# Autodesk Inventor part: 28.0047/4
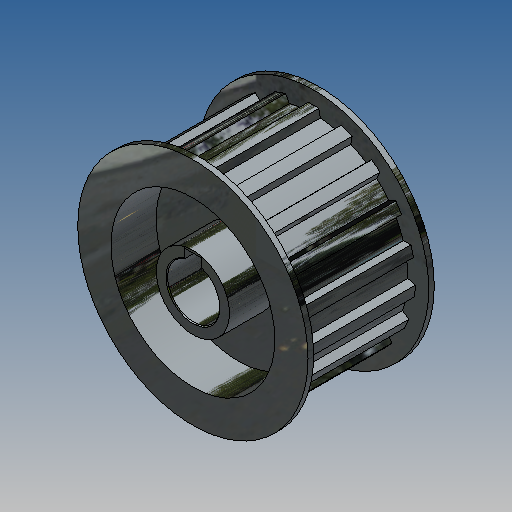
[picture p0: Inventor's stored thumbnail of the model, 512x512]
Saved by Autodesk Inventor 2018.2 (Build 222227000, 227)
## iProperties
Created: 2006-12
Document SubType Name: Modeling
Designer: Andy Moles
Material: Aluminum-6061
Part Number: 28.0047/4
Density: 2.7 g/cm^3
Description: Timing Belt Pulley T45, 15mm Bore & Key
Mass: 131.491 g
Surface Area: 244.333 cm^2
Volume: 48.7006 cm^3
Appearance: Zinc
Author: Andy Moles
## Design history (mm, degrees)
sketch "Sketch1"
  geometry: L1 (-1.927, 26.982)-(-1.524, 29.17); L2 (1.927, 26.982)-(1.524, 29.17); L3 (11.073, 27.03)-(10.707, 24.842); L4 (15.084, 22.455)-(16.683, 23.977); L5 (19.077, 22.12)-(18.136, 20.071); L6 (21.534, 16.371)-(23.587, 17.23); L7 (25.254, 14.678)-(23.643, 13.144); L8 (25.717, 8.391)-(27.944, 8.508); L9 (28.652, 5.683)-(26.63, 4.755); L10 (27.049, -0.307)-(29.196, -0.889); L11 (28.945, -3.928)-(26.741, -4.085); L12 (25.484, -9.074)-(27.339, -10.286); L13 (26.084, -13.147)-(23.954, -12.569); L14 (21.157, -16.857)-(22.493, -18.635); L15 (20.429, -20.878)-(18.546, -19.693); L16 (14.537, -22.813)-(15.224, -24.929); L17 (12.543, -26.38)-(11.147, -24.648); L18 (6.342, -26.297)-(6.304, -28.522); L19 (3.298, -29.023)-(2.54, -26.931); L20 (-2.54, -26.931)-(-3.298, -29.023); L21 (-6.304, -28.522)-(-6.342, -26.297); L22 (-11.183, -24.631)-(-12.509, -26.396); L23 (-15.224, -24.929)-(-14.537, -22.813); L24 (-18.546, -19.693)-(-20.429, -20.878); L25 (-22.494, -18.635)-(-21.157, -16.856); L26 (-23.935, -12.604)-(-26.101, -13.113); L27 (-27.325, -10.322)-(-25.484, -9.074); L28 (-26.731, -4.15)-(-28.945, -3.928); L29 (-29.196, -0.89)-(-27.049, -0.307); L30 (-26.63, 4.756)-(-28.652, 5.685); L31 (-27.892, 8.674)-(-25.696, 8.455); L32 (-23.643, 13.144)-(-25.254, 14.679); L33 (-23.587, 17.23)-(-21.534, 16.371); L34 (-18.094, 20.109)-(-19.119, 22.083); L35 (-16.714, 23.955)-(-15.052, 22.477); L36 (-10.707, 24.842)-(-11.073, 27.03); L37 (-8.03, 28.085)-(-6.938, 26.146); L38 (6.938, 26.146)-(7.851, 28.135); A1 r 29.21 centre (0, 0) between (-16.714, 23.955) and (-19.119, 22.083); A2 r 27.051 centre (0, 0) between (-10.707, 24.842) and (-15.052, 22.477); A3 r 29.21 centre (0, 0) between (-8.03, 28.085) and (-11.073, 27.03); A4 r 27.051 centre (0, 0) between (-1.927, 26.982) and (-6.938, 26.146); A5 r 29.21 centre (0, 0) between (1.524, 29.17) and (-1.524, 29.17); A6 r 29.21 centre (0, 0) between (11.073, 27.03) and (7.851, 28.135); A7 r 29.21 centre (0, 0) between (19.077, 22.12) and (16.683, 23.977); A8 r 27.051 centre (0, 0) between (15.084, 22.455) and (10.707, 24.842); A9 r 27.051 centre (0, 0) between (21.534, 16.371) and (18.136, 20.071); A10 r 29.21 centre (0, 0) between (25.254, 14.678) and (23.587, 17.23); A11 r 27.051 centre (0, 0) between (25.717, 8.391) and (23.643, 13.144); A12 r 29.21 centre (0, 0) between (28.652, 5.683) and (27.944, 8.508); A13 r 27.051 centre (0, 0) between (27.049, -0.307) and (26.63, 4.755); A14 r 29.21 centre (0, 0) between (28.945, -3.928) and (29.196, -0.889); A15 r 27.051 centre (0, 0) between (25.484, -9.074) and (26.741, -4.085); A16 r 29.21 centre (0, 0) between (26.084, -13.147) and (27.339, -10.286); A17 r 27.051 centre (0, 0) between (21.157, -16.857) and (23.954, -12.569); A18 r 29.21 centre (0, 0) between (20.429, -20.878) and (22.493, -18.635); A19 r 27.051 centre (0, 0) between (14.537, -22.813) and (18.546, -19.693); A20 r 29.21 centre (0, 0) between (12.543, -26.38) and (15.224, -24.929); A21 r 27.051 centre (0, 0) between (6.342, -26.297) and (11.147, -24.648); A22 r 29.21 centre (0, 0) between (3.298, -29.023) and (6.304, -28.522); A23 r 27.051 centre (0, 0) between (-2.54, -26.931) and (2.54, -26.931); A24 r 29.21 centre (0, 0) between (-6.304, -28.522) and (-3.298, -29.023); A25 r 29.21 centre (0, 0) between (-15.224, -24.929) and (-12.509, -26.396); A26 r 29.21 centre (0, 0) between (-22.494, -18.635) and (-20.429, -20.878); A27 r 27.051 centre (0, 0) between (-11.183, -24.631) and (-6.342, -26.297); A28 r 27.051 centre (0, 0) between (-18.546, -19.693) and (-14.537, -22.813); A29 r 29.21 centre (0, 0) between (-27.325, -10.322) and (-26.101, -13.113); A30 r 27.051 centre (0, 0) between (-23.935, -12.604) and (-21.157, -16.856); A31 r 27.051 centre (0, 0) between (-26.731, -4.15) and (-25.484, -9.074); A32 r 29.21 centre (0, 0) between (-29.196, -0.89) and (-28.945, -3.928); A33 r 27.051 centre (0, 0) between (-26.63, 4.756) and (-27.049, -0.307); A34 r 29.21 centre (0, 0) between (-23.587, 17.23) and (-25.254, 14.679); A35 r 29.21 centre (0, 0) between (-27.892, 8.674) and (-28.652, 5.685); A36 r 27.051 centre (0, 0) between (-18.094, 20.109) and (-21.534, 16.371); A37 r 27.051 centre (0, 0) between (-23.643, 13.144) and (-25.696, 8.455); A38 r 27.051 centre (0, 0) between (6.938, 26.146) and (1.927, 26.982); 2 further points
  constraints: 77 point on circle, 76 end point, 38 centre point, 4 parallel, 2 coincident, 2 perpendicular
extrude "Extrusion1" new body sketch "Sketch1" stored distance "d19" = 33; taper "d20" = 0 deg
sketch "Sketch4"
  geometry: C1 r 33.02 at (0, 0); A1 r 27.051 centre (0, 0) between (6.938, 26.146) and (1.927, 26.982) reference
  constraints: 1 centre point, 1 coincident
  dimensions: "d24" = 66.04 diameter of C1
extrude "Extrusion3" join sketch "Sketch4" distance "d25" = 1.6; taper "d26" = 0 deg
sketch "Sketch5"
  geometry: C1 r 33.02 at (0, 0) reference; C2 r 10.5 at (0, 0); C3 r 23.5 at (0, 0)
  constraints: 2 centre point, 2 coincident
  dimensions: "d27" = 21 diameter of C2; "d28" = 47 diameter of C3
extrude "Extrusion4" cut sketch "Sketch5" distance "d29" = 12.954; taper "d30" = 0 deg
mirror "Mirror1"
sketch "Sketch6"
  geometry: L1 (-2.5, 7.071)-(-2.5, 9.8); L2 (-2.5, 9.8)-(2.5, 9.8); L3 (2.5, 9.8)-(2.5, 7.071); C1 r 10.5 at (0, 0) reference; A1 r 7.5 centre (0, 0) between (-2.5, 7.071) and (2.5, 7.071); 1 further point
  constraints: 6 end point, 2 point on circle, 1 centre point, 1 coincident, 1 midpoint, 1 parallel, 1 perpendicular, 1 vertical, 1 vertical alignment
  dimensions: "d31" = 15 diameter of A1 (= SHAFT_DIA); "d34" = 5 distance of L1.end L2.end (= SQUARE_KEY_SIZE); "d35" = 17.3 dimension on A1 L2 (= SHAFT_DIA + t2_KEYWAY_DEPTH)
extrude "Extrusion5" cut sketch "Sketch6" extent not by distance; stored distance "d32" = 12.954; taper "d33" = 0 deg
chamfer "Chamfer1" distance "d36" = 0.25; stored, may be unused: second distance "d37" = 2, angle "d38" = 45 deg
body "Solid1"
other parameters: "d1" = 2.159, "SHAFT_DIA" = 15 [user parameter; used in 2 equation terms], "SQUARE_KEY_SIZE" = 5 [user parameter; used in 1 equation term], "t2_KEYWAY_DEPTH" = 2.3 [user parameter; used in 1 equation term]
